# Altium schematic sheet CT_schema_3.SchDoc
size 288 x 169 mm
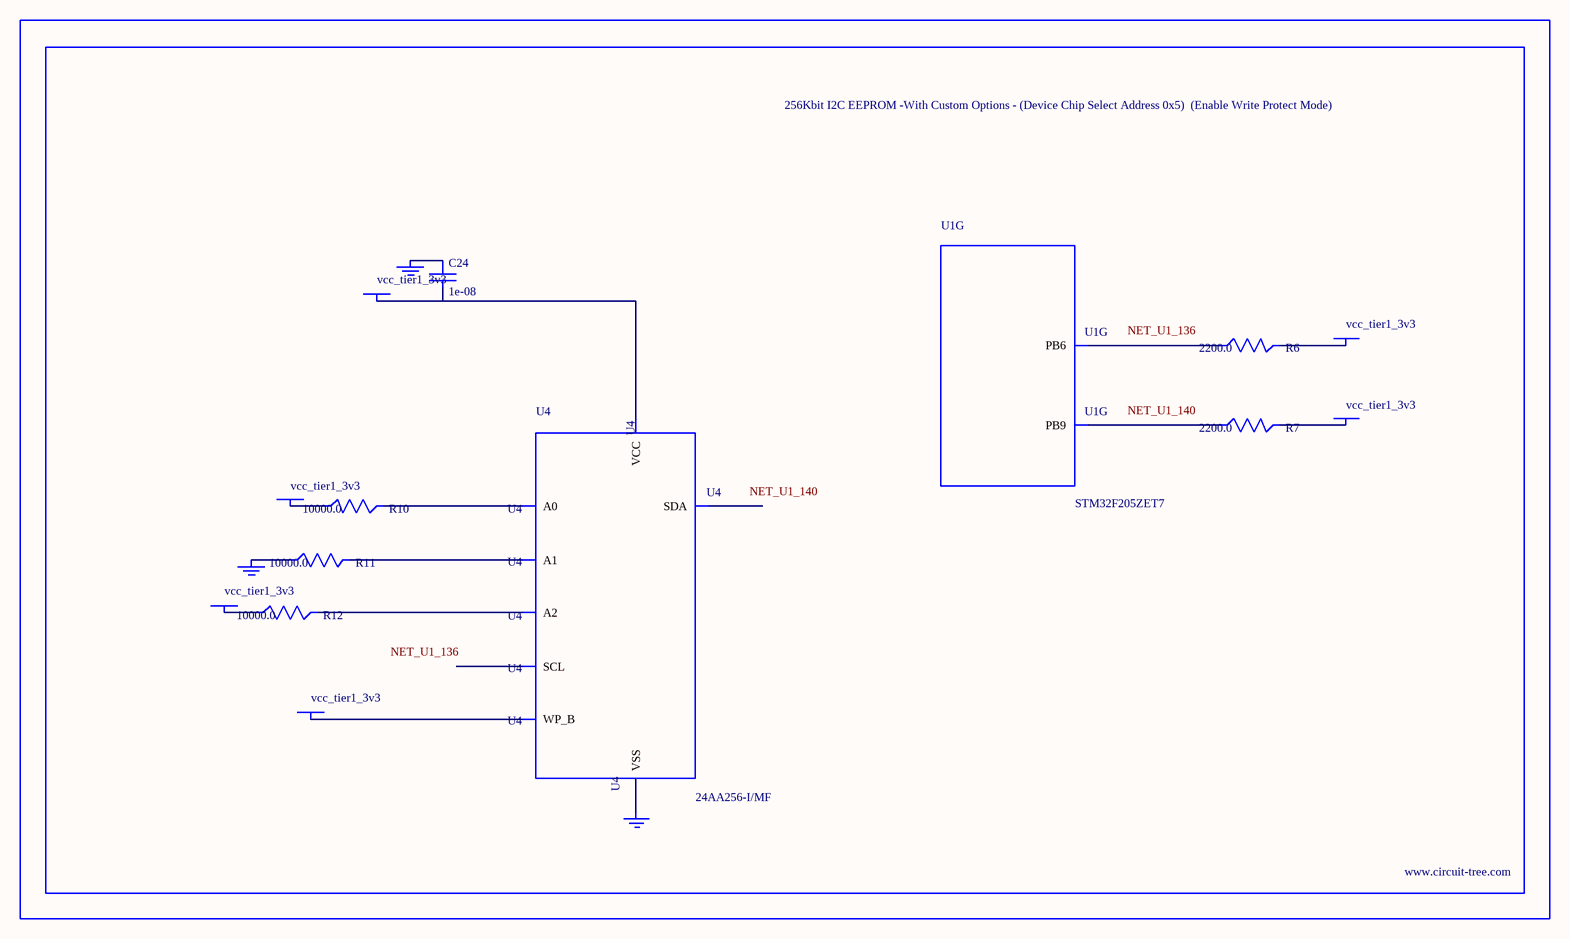
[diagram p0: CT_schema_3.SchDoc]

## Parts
BORDER2  (no value)
C24  1e-08  [C0402]
GND_INSTANCE_2_0  (no value)
GND_INSTANCE_2_1  (no value)
GND_INSTANCE_2_2  (no value)
POWER_INSTANCE_2_0  vcc_tier1_3v3
POWER_INSTANCE_2_1  vcc_tier1_3v3
POWER_INSTANCE_2_2  vcc_tier1_3v3
POWER_INSTANCE_2_3  vcc_tier1_3v3
POWER_INSTANCE_2_4  vcc_tier1_3v3
POWER_INSTANCE_2_5  vcc_tier1_3v3
R6  2200.0  [R0603]
R7  2200.0  [R0603]
R10  10000.0  [R0603]
R11  10000.0  [R0603]
R12  10000.0  [R0603]
U1  STM32F205ZET7  [LQFP144]  (part G of 13)
U4  24AA256-I/MF  [DFN8-S]

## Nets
NetC24_1: C24.1 GND_INSTANCE_2_1.0(GND)
NetC24_2: C24.2 POWER_INSTANCE_2_3.0(PWR) U4.8(VCC)
NetGND_INSTANCE_2_0_0: GND_INSTANCE_2_0.0(GND) R11.1
NetGND_INSTANCE_2_2_0: GND_INSTANCE_2_2.0(GND) U4.4(VSS)
NetPOWER_INSTANCE_2_0_0: POWER_INSTANCE_2_0.0(PWR) R10.1
NetPOWER_INSTANCE_2_1_0: POWER_INSTANCE_2_1.0(PWR) R12.1
NetPOWER_INSTANCE_2_2_0: POWER_INSTANCE_2_2.0(PWR) U4.7(WP_B)
NetPOWER_INSTANCE_2_4_0: POWER_INSTANCE_2_4.0(PWR) R6.2
NetPOWER_INSTANCE_2_5_0: POWER_INSTANCE_2_5.0(PWR) R7.2
NetR6_1: R6.1 U1.136(PB6)
NetR7_1: R7.1 U1.140(PB9)
NetR10_2: R10.2 U4.1(A0)
NetR11_2: R11.2 U4.2(A1)
NetR12_2: R12.2 U4.3(A2)

Not connected (* = marked no-connect by the designer): U4 5(SDA) 6(SCL)

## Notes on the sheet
- Labels drawn without touching a wire or pin: NET_U1_136, NET_U1_140

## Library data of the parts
BORDER2 = BORDER_PAGE2
C24 = C0402C103K3RAC
GND_INSTANCE_2_0-GND_INSTANCE_2_2 = GND
POWER_INSTANCE_2_0-POWER_INSTANCE_2_5 = PWR
R6 R7 = RC0603JR-072K2L
R10-R12 = RC0603JR-0710KL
